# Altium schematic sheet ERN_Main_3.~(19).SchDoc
size A; SheetNumber: 3; SheetTotal: 3; SPICEModelCacheXVWYUVSQ: <root> / <DocumentId>XVWYUVSQ</DocumentId> / <CacheFrame Number="0"> / <Model Name="irf1010" Kind="CKT"> / <Text>*IRF1010 MCE 4-2-96 / *55V  75A .014 ohm HEXFET pkg:TO-220 2,1,3 / .SUBCKT IRF1010  10 20 40 40 / M1   1  2  3  3  DMOS L=1U W=1U / RD  10  1  5.65M / RS  30  3  1.35M / RG  20  2  12.1 / CGS  2  3  2.15N / EGD 12  0  2  1  1 / VFB 14  0  0 / FFB  2  1  VFB  1 / CGD 13 14  4.49N / R1  13  0  1 / D1  12 13  DLIM / DDG 15 14  DCGD / R2  12 15  1 / D2  15  0  DLIM / DSD  3 10  DSUB / LS  30 40  7.5N / .MODEL DMOS NMOS (LEVEL=3 THETA=60M VMAX=114K ETA=2M VTO=3 KP=19.4) / .MODEL DCGD D (CJO=4.49N VJ=.6 M=.68) / .MODEL DSUB D (IS=311N N=1.5 RS=8.67M BV=55 CJO=4.08N VJ=.8 M=.42 TT=100N) / .MODEL DLIM D (IS=100U) / .ENDS IRF1010</Text> / </Model> / <Model Name="1n5400" Kind="MDL"> / <Text>*1N5400 MCE / * 50V 3A Si Rectifier pkg:DO-201 1,2 / .MODEL 1N5400 D(IS=2.68E-12 RS=0.00977 N=1.17 TT=1.44E-5 CJO=1.24E-10 / + VJ=0.6 M=0.333 BV=66.6 IBV=1E-5 )</Text> / </Model> / </CacheFrame> / </root>
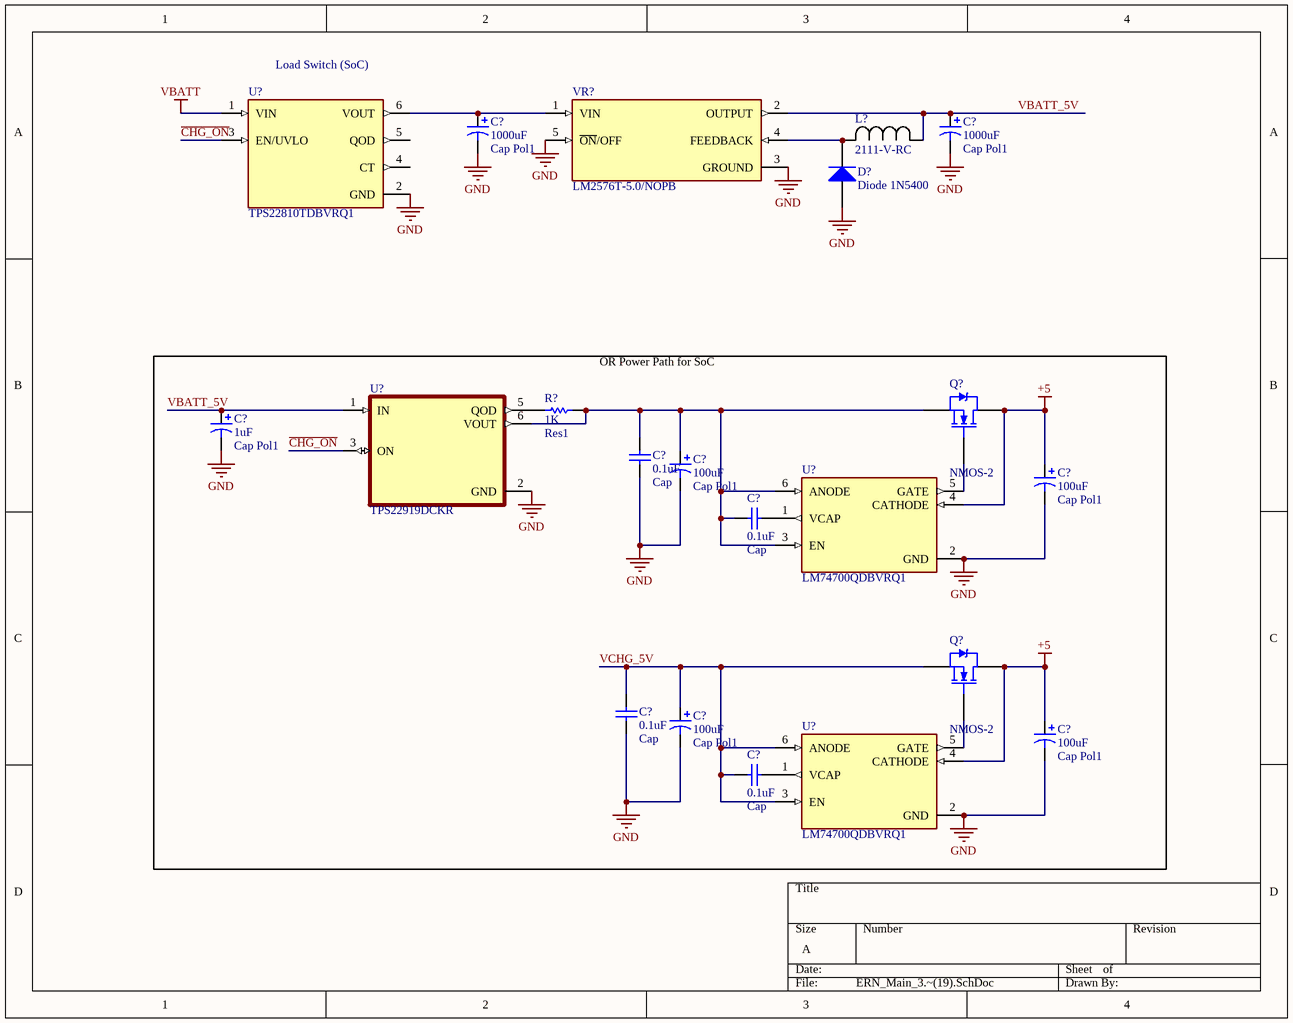
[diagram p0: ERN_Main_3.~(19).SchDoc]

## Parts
(Parts that share a designator on the sheet are numbered #1, #2 ... from top to bottom, then left to right.)
C?#1  Cap Pol1  value 1000uF  [RB7.6-15]
C?#2  Cap Pol1  value 1000uF  [RB7.6-15]
C?#3  Cap Pol1  value 1uF  [RB7.6-15]
C?#4  Cap  value 0.1uF  [RAD-0.3]
C?#5  Cap Pol1  value 100uF  [RB7.6-15]
C?#6  Cap Pol1  value 100uF  [RB7.6-15]
C?#7  Cap  value 0.1uF  [RAD-0.3]
C?#8  Cap  value 0.1uF  [RAD-0.3]
C?#9  Cap Pol1  value 100uF  [RB7.6-15]
C?#10  Cap Pol1  value 100uF  [RB7.6-15]
C?#11  Cap  value 0.1uF  [RAD-0.3]
D?  Diode 1N5400  [DO-201AD]
L?  2111-V-RC  [IND_21XX_27A_V]
Q?#1  NMOS-2  [TO-220AB]
Q?#2  NMOS-2  [TO-220AB]
R?  Res1  value 1K  [AXIAL-0.3]
U?#1  TPS22810TDBVRQ1  [SOT95P280X145-6N]
U?#2  TPS22919DCKR  [SOT65P210X110-6N]
U?#3  LM74700QDBVRQ1  [SOT95P280X145-6N]
U?#4  LM74700QDBVRQ1  [SOT95P280X145-6N]
VR?  LM2576T-5.0/NOPB  [TO170P1067X483X1651-5]

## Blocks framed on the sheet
OR Power Path for SoC: C?#3-C?#11 Q?#1 Q?#2 R? U?#2-U?#4

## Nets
+5: C?#6.1 C?#10.1 Q?#1.2(D) Q?#2.2(D) U?#3.4(CATHODE) U?#4.4(CATHODE)
GND: C?#1.2 C?#2.2 C?#3.2 C?#4.1 C?#5.2 C?#6.2 C?#8.1 C?#9.2 C?#10.2 D?.1(A) U?#1.2(GND) U?#2.2(GND) U?#3.2(GND) U?#4.2(GND) VR?.3(GROUND) VR?.5(~{ON}/OFF)
VBATT: U?#1.1(VIN)
~{CHG_ON}: U?#1.3(EN/UVLO) U?#2.3(ON)
VBATT_5V: C?#2.1 C?#3.1 L?.1 U?#2.1(IN) VR?.2(OUTPUT)
VCHG_5V: C?#8.2 C?#9.1 C?#11.2 Q?#2.3(S) U?#4.3(EN) U?#4.6(ANODE)
NetC?#1_1: C?#1.1 U?#1.6(VOUT) VR?.1(VIN)
NetC?#4_2: C?#4.2 C?#5.1 C?#7.2 Q?#1.3(S) R?.1 U?#2.6(VOUT) U?#3.3(EN) U?#3.6(ANODE)
NetC?#7_1: C?#7.1 U?#3.1(VCAP)
NetC?#11_1: C?#11.1 U?#4.1(VCAP)
NetD?_2: D?.2(K) L?.2 VR?.4(FEEDBACK)
NetQ?#1_1: Q?#1.1(G) U?#3.5(GATE)
NetQ?#2_1: Q?#2.1(G) U?#4.5(GATE)
NetR?_2: R?.2 U?#2.5(QOD)

Not connected (* = marked no-connect by the designer): U?#1 4(CT) 5(QOD)

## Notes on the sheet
- (near U?#1) Load Switch (SoC)

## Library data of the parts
C?#1-C?#3 C?#5 C?#6 C?#9 C?#10 = Cap Pol1: Polarized Capacitor (Radial)
C?#4 C?#7 C?#8 C?#11 = Cap: Capacitor
D? = Diode 1N5400: 3 Amp General Purpose Rectifier
L? = 2111-V-RC: Inductor 68uH; Manufacturer_Name: Bourns Electronics
Q?#1 Q?#2 = NMOS-2: N-Channel Power MOSFET; Note: Pin 2 is electrically connected to pin 4.
R? = Res1: Resistor
U?#1 = TPS22810TDBVRQ1: Automotive 1-channel, 18-V, 2-A, 79-mâ„¦ load switch with adj. rise time and adj. output discharge; MF: Texas Instruments
U?#2 = TPS22919DCKR: 5.5-V, 1.5-A, 90-mÎ© load switch with adj. output discharge; MF: Texas Instruments
U?#3 U?#4 = LM74700QDBVRQ1: 3.2-V to 65-V, 80-uA IQ automotive ideal diode controller; MF: Texas Instruments
VR? = LM2576T-5.0/NOPB: SIMPLE SWITCHERÂ® 40V, 3A Low Component Count Step-Down Regulator; MF: Texas Instruments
